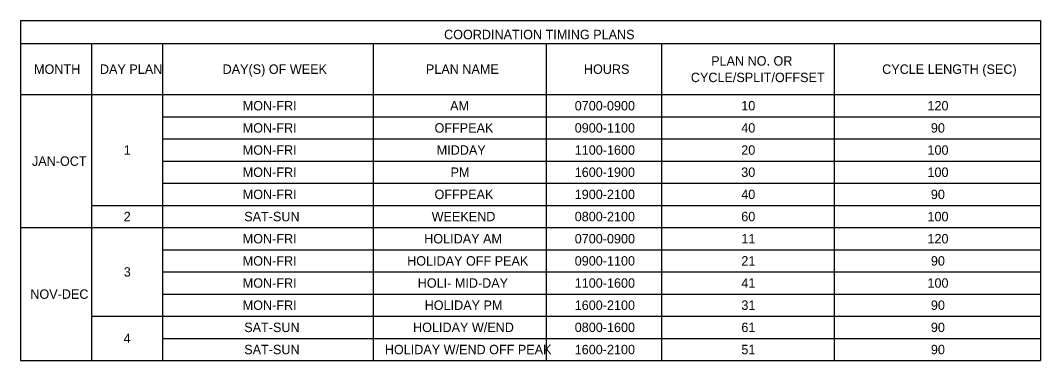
# Model space of a CAD drawing. Extents: x 0 to 680, y -289 to 440.
# Drawn here: x 344.9 to 648, y -288.7 to -187.6 of the extents above; entities that cross this region are included whole.
import ezdxf

# ---------------------------------------------------------------- set-up
doc = ezdxf.new("R2010")
doc.units = 0
doc.layers.add('Default', color=7, linetype='Continuous')

msp = doc.modelspace()

# ---------------------------------------------------------------- linework, layer by layer
at = {"layer": 'Default'}
for p, q in [((344.9, -187.55), (647.96, -187.55)), ((344.9, -187.55), (344.9, -288.68)), ((647.96, -187.55), (647.96, -288.68)), ((344.9, -194.47), (647.96, -194.47)), ((365.99, -194.47), (365.99, -288.68)), ((387.07, -194.47), (387.07, -288.68)), ((449.66, -194.47), (449.66, -288.68)), ((501.05, -194.47), (501.05, -288.68)), ((535.3, -194.47), (535.3, -288.68)), ((586.69, -194.47), (586.69, -288.68)), ((344.9, -209.62), (647.96, -209.62)), ((387.07, -216.21), (647.96, -216.21)), ((387.07, -222.8), (647.96, -222.8)), ((387.07, -229.39), (647.96, -229.39)), ((387.07, -235.98), (647.96, -235.98)), ((365.99, -242.56), (647.96, -242.56)), ((344.9, -249.15), (647.96, -249.15)), ((387.07, -255.74), (647.96, -255.74)), ((387.07, -262.33), (647.96, -262.33)), ((387.07, -268.92), (647.96, -268.92)), ((365.99, -275.51), (647.96, -275.51)), ((387.07, -282.09), (647.96, -282.09)), ((344.9, -288.68), (647.96, -288.68))]:
    msp.add_line(p, q, dxfattribs=at)

# ---------------------------------------------------------------- texts
for s, p in [('COORDINATION TIMING PLANS', (470.76, -193.15)), ('PLAN NO. OR', (550.1, -201)), ('MONTH', (348.96, -203.45)), ('DAY PLAN', (368.53, -203.45)), ('DAY(S) OF WEEK', (404.97, -203.45)), ('PLAN NAME', (465.37, -203.45)), ('HOURS', (512.3, -203.45)), ('CYCLE/SPLIT/OFFSET', (544.07, -205.9)), ('CYCLE LENGTH (SEC)', (600.9, -203.45)), ('MON-FRI', (410.95, -214.32)), ('AM', (472.55, -214.32)), ('0700-0900', (509.57, -214.32)), ('10', (559.04, -214.32)), ('120', (614.36, -214.32)), ('MON-FRI', (410.95, -220.91)), ('OFFPEAK', (467.93, -220.91)), ('0900-1100', (509.57, -220.91)), ('40', (559.04, -220.91)), ('90', (615.37, -220.91)), ('1', (375.61, -227.49)), ('MON-FRI', (410.95, -227.49)), ('MIDDAY', (468.57, -227.49)), ('1100-1600', (509.57, -227.49)), ('20', (559.04, -227.49)), ('100', (614.36, -227.49)), ('JAN-OCT', (348.34, -230.79)), ('MON-FRI', (410.95, -234.08)), ('PM', (472.7, -234.08)), ('1600-1900', (509.57, -234.08)), ('30', (559.04, -234.08)), ('100', (614.36, -234.08)), ('MON-FRI', (410.95, -240.67)), ('OFFPEAK', (467.93, -240.67)), ('1900-2100', (509.57, -240.67)), ('40', (559.04, -240.67)), ('90', (615.37, -240.67)), ('2', (375.6, -247.26)), ('SAT-SUN', (411.4, -247.26)), ('WEEKEND', (467.07, -247.26)), ('0800-2100', (509.57, -247.26)), ('60', (559.04, -247.26)), ('100', (614.36, -247.26)), ('MON-FRI', (410.95, -253.85)), ('HOLIDAY AM', (464.86, -253.85)), ('0700-0900', (509.57, -253.85)), ('11', (559.08, -253.85)), ('120', (614.36, -253.85)), ('MON-FRI', (410.95, -260.44)), ('HOLIDAY OFF PEAK', (459.79, -260.44)), ('0900-1100', (509.57, -260.44)), ('21', (559.08, -260.44)), ('90', (615.37, -260.44)), ('3', (375.61, -263.73)), ('MON-FRI', (410.95, -267.02)), ('HOLI- MID-DAY', (462.94, -267.02)), ('1100-1600', (509.57, -267.02)), ('41', (559.08, -267.02)), ('100', (614.36, -267.02)), ('NOV-DEC', (347.85, -270.32)), ('MON-FRI', (410.95, -273.61)), ('HOLIDAY PM', (465, -273.61)), ('1600-2100', (509.57, -273.61)), ('31', (559.08, -273.61)), ('90', (615.37, -273.61)), ('SAT-SUN', (411.4, -280.2)), ('HOLIDAY W/END', (461.55, -280.2)), ('0800-1600', (509.57, -280.2)), ('61', (559.08, -280.2)), ('90', (615.37, -280.2)), ('4', (375.56, -283.49)), ('SAT-SUN', (411.4, -286.79)), ('HOLIDAY W/END OFF PEAK', (453.16, -286.79)), ('1600-2100', (509.57, -286.79)), ('51', (559.08, -286.79)), ('90', (615.37, -286.79))]:
    msp.add_text(s, height=2.8, dxfattribs=at).set_placement(p)

doc.saveas('drawing.dxf')
